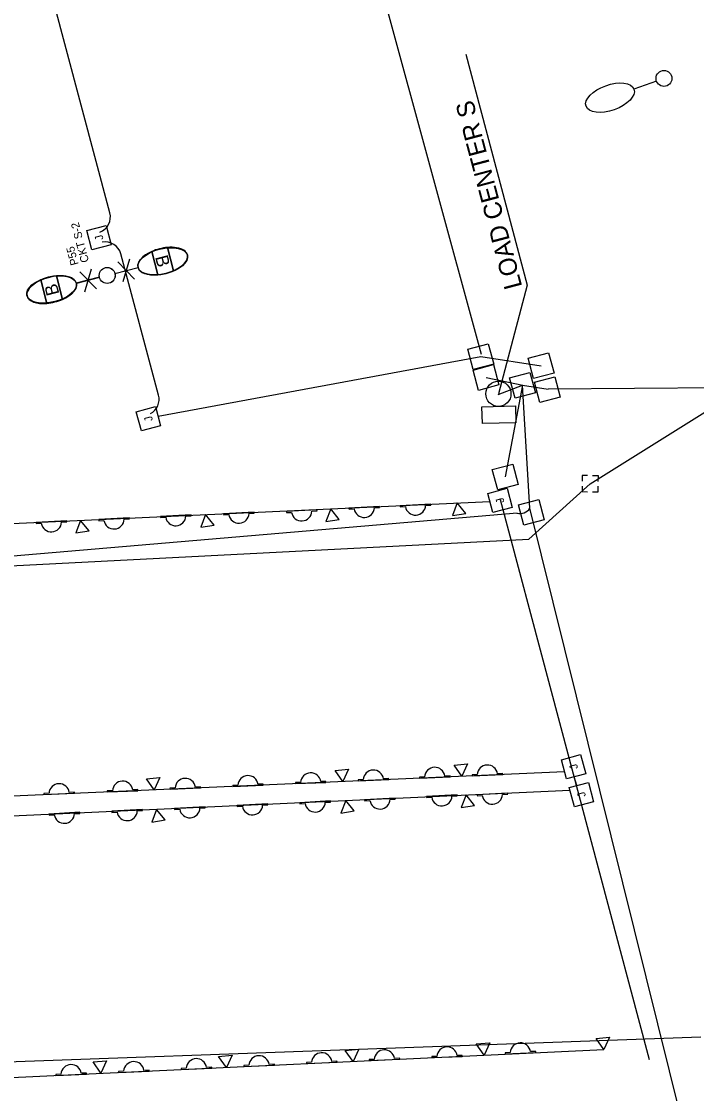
# Model space of a CAD drawing. Extents: x 925407 to 931638, y 609358 to 637063.
# Drawn here: x 930544.2 to 930754.2, y 629284.3 to 629618 of the extents above; entities that cross this region are included whole.
import ezdxf

# ---------------------------------------------------------------- set-up
doc = ezdxf.new("R2010")
doc.units = 0
for name, color, linetype in [('ActivePointCell_dp', 7, 'Continuous'), ('Bridge', 7, 'Continuous'), ('Conduit', 7, 'Continuous'), ('ConduitDB', 7, 'Continuous'), ('ConduitJB', 7, 'Continuous'), ('ConduitOT', 7, 'Continuous'), ('JunctBoxA', 7, 'Continuous'), ('LightingMisc', 7, 'Continuous'), ('LoadCenter', 7, 'Continuous'), ('Miscellaneous2', 7, 'Continuous'), ('PoleLight', 7, 'Continuous'), ('PoleLight_ep', 7, 'Continuous'), ('PullBox', 7, 'Continuous'), ('TextLabel', 7, 'Continuous')]:
    doc.layers.add(name, color=color, linetype=linetype)

msp = doc.modelspace()

# ---------------------------------------------------------------- linework, layer by layer
at = {"layer": 'ActivePointCell_dp'}
msp.add_line((930682.43, 629607.84), (930701.48, 629535.86), dxfattribs=at)
msp.add_lwpolyline([(930701.48, 629535.86), (930692.57, 629502.08)], dxfattribs=at)
at = {"layer": 'Bridge'}
msp.add_line((930739.58, 629294.85), (930693.25, 629469.11), dxfattribs=at)
msp.add_line((930739.58, 629294.85), (930693.25, 629469.11), dxfattribs=at)
msp.add_line((930739.58, 629294.85), (930693.25, 629469.11), dxfattribs=at)
at = {"layer": 'Conduit'}
for p, q in [((930721.08, 629474.1), (930780.76, 629511.4)), ((930702, 629456.89), (930721.08, 629474.1)), ((930495.19, 629446.22), (930702, 629456.89)), ((930519.05, 629293.47), (930755.53, 629302.01))]:
    msp.add_line(p, q, dxfattribs=at)
at = {"layer": 'ConduitDB'}
for p, q in [((930586.7, 629495.1), (930687.09, 629513.65)), ((930784.91, 629504.06), (930708.05, 629503.58)), ((930486.25, 629446.88), (930698.37, 629465.04)), ((930749.58, 629276.27), (930702.37, 629466.49))]:
    msp.add_line(p, q, dxfattribs=at)
msp.add_arc((930699.31, 629468.51), 3.66, 254.0135, 326.5788, dxfattribs=at)
at = {"layer": 'ConduitJB'}
for p, q in [((930490.97, 629459.39), (930689.95, 629468.59)), ((930713.18, 629384.45), (930513.24, 629375.62)), ((930716.95, 629380.16), (930716.18, 629382.87)), ((930514.85, 629369.56), (930714.83, 629378.73)), ((930536.26, 629289.06), (930725.41, 629297.99))]:
    msp.add_line(p, q, dxfattribs=at)
at = {"layer": 'ConduitOT'}
for p, q in [((930630.48, 629722.29), (930687.25, 629514.41)), ((930571.71, 629558.43), (930548.86, 629644.47)), ((930586.85, 629501.67), (930575.11, 629545.66)), ((930687.09, 629513.65), (930705.86, 629510.82)), ((930688.72, 629507.17), (930700.2, 629504.81)), ((930692.54, 629501.84), (930700.07, 629504.76)), ((930700.07, 629504.76), (930694.69, 629476.22)), ((930702.37, 629466.49), (930700.07, 629504.76)), ((930700.07, 629504.76), (930708.05, 629503.58))]:
    msp.add_line(p, q, dxfattribs=at)
for centre, start, end in [((930566.88, 629557.14), 289.9661, 14.8904), ((930570.28, 629544.36), 14.8905, 101.353), ((930582.03, 629500.37), 297.939, 15.0625)]:
    msp.add_arc(centre, 5, start, end, dxfattribs=at)
at = {"layer": 'LightingMisc'}
for p, q in [((930616.6, 629465.24), (930607.09, 629464.71)), ((930615.01, 629464.84), (930616.61, 629464.92)), ((930616.61, 629464.92), (930616.6, 629465.24)), ((930636.14, 629465.96), (930626.63, 629465.43)), ((930626.63, 629465.43), (930626.65, 629465.11)), ((930626.65, 629465.11), (930628.25, 629465.2)), ((930634.56, 629465.55), (930636.16, 629465.64)), ((930636.16, 629465.64), (930636.14, 629465.96)), ((930655.58, 629467.04), (930646.08, 629466.51)), ((930646.08, 629466.51), (930646.1, 629466.2)), ((930646.1, 629466.2), (930647.7, 629466.29)), ((930654, 629466.64), (930655.6, 629466.73)), ((930655.6, 629466.73), (930655.58, 629467.04)), ((930671.52, 629467.78), (930662.02, 629467.25)), ((930662.02, 629467.25), (930662.03, 629466.93)), ((930662.03, 629466.93), (930663.63, 629467.02)), ((930669.94, 629467.37), (930671.54, 629467.46)), ((930671.54, 629467.46), (930671.52, 629467.78)), ((930558.27, 629462.55), (930548.77, 629462.02)), ((930548.77, 629462.02), (930548.78, 629461.7)), ((930548.78, 629461.7), (930550.38, 629461.79)), ((930556.69, 629462.14), (930558.29, 629462.23)), ((930558.29, 629462.23), (930558.27, 629462.55)), ((930577.76, 629463.45), (930568.26, 629462.92)), ((930568.26, 629462.92), (930568.28, 629462.6)), ((930568.28, 629462.6), (930569.88, 629462.69)), ((930576.18, 629463.04), (930577.78, 629463.13)), ((930577.78, 629463.13), (930577.76, 629463.45)), ((930596.95, 629464.46), (930587.45, 629463.93)), ((930587.45, 629463.93), (930587.47, 629463.61)), ((930587.47, 629463.61), (930589.07, 629463.7)), ((930595.37, 629464.05), (930596.97, 629464.14)), ((930596.97, 629464.14), (930596.95, 629464.46)), ((930607.09, 629464.71), (930607.11, 629464.4)), ((930607.11, 629464.4), (930608.71, 629464.49)), ((930638.93, 629381.47), (930637.33, 629381.41)), ((930638.94, 629381.16), (930638.93, 629381.47)), ((930650.52, 629382.01), (930648.92, 629381.94)), ((930648.92, 629381.94), (930648.93, 629381.63)), ((930648.93, 629381.63), (930658.45, 629382.02)), ((930658.43, 629382.33), (930656.83, 629382.27)), ((930658.45, 629382.02), (930658.43, 629382.33)), ((930669.61, 629382.86), (930668.01, 629382.79)), ((930668.01, 629382.79), (930668.02, 629382.47)), ((930668.02, 629382.47), (930677.53, 629382.86)), ((930677.52, 629383.18), (930675.92, 629383.11)), ((930677.53, 629382.86), (930677.52, 629383.18)), ((930685.97, 629383.57), (930684.37, 629383.51)), ((930684.37, 629383.51), (930684.38, 629383.19)), ((930684.38, 629383.19), (930693.9, 629383.58)), ((930693.88, 629383.9), (930692.28, 629383.83)), ((930693.9, 629383.58), (930693.88, 629383.9)), ((930560.69, 629378.08), (930559.09, 629378.01)), ((930560.7, 629377.76), (930560.69, 629378.08)), ((930572.51, 629378.56), (930570.91, 629378.5)), ((930570.91, 629378.5), (930570.92, 629378.18)), ((930570.92, 629378.18), (930580.43, 629378.57)), ((930580.42, 629378.89), (930578.82, 629378.82)), ((930580.43, 629378.57), (930580.42, 629378.89)), ((930592.01, 629379.43), (930590.41, 629379.36)), ((930590.41, 629379.36), (930590.42, 629379.04)), ((930590.42, 629379.04), (930599.93, 629379.43)), ((930599.92, 629379.75), (930598.32, 629379.68)), ((930599.93, 629379.43), (930599.92, 629379.75)), ((930611.51, 629380.29), (930609.91, 629380.22)), ((930609.91, 629380.22), (930609.93, 629379.9)), ((930609.93, 629379.9), (930619.44, 629380.29)), ((930619.43, 629380.61), (930617.82, 629380.55)), ((930619.44, 629380.29), (930619.43, 629380.61)), ((930631.02, 629381.15), (930629.42, 629381.08)), ((930629.42, 629381.08), (930629.43, 629380.77)), ((930629.43, 629380.77), (930638.94, 629381.16)), ((930552.78, 629377.76), (930551.18, 629377.69)), ((930551.18, 629377.69), (930551.19, 629377.37)), ((930551.19, 629377.37), (930560.7, 629377.76)), ((930640.31, 629375.36), (930630.81, 629374.83)), ((930630.81, 629374.83), (930630.82, 629374.52)), ((930638.73, 629374.95), (930640.33, 629375.04)), ((930640.33, 629375.04), (930640.31, 629375.36)), ((930660.47, 629376.28), (930650.96, 629375.76)), ((930650.96, 629375.76), (930650.98, 629375.44)), ((930650.98, 629375.44), (930652.58, 629375.53)), ((930658.89, 629375.88), (930660.49, 629375.97)), ((930660.49, 629375.97), (930660.47, 629376.28)), ((930679.71, 629377.26), (930670.21, 629376.74)), ((930670.21, 629376.74), (930670.22, 629376.42)), ((930670.22, 629376.42), (930671.82, 629376.51)), ((930678.13, 629376.86), (930679.73, 629376.95)), ((930679.73, 629376.95), (930679.71, 629377.26)), ((930695.45, 629377.81), (930685.94, 629377.28)), ((930685.94, 629377.28), (930685.96, 629376.96)), ((930685.96, 629376.96), (930687.56, 629377.05)), ((930693.86, 629377.4), (930695.46, 629377.49)), ((930695.46, 629377.49), (930695.45, 629377.81)), ((930562.32, 629371.84), (930552.81, 629371.31)), ((930560.73, 629371.43), (930562.33, 629371.52)), ((930562.33, 629371.52), (930562.32, 629371.84)), ((930581.83, 629372.68), (930572.32, 629372.15)), ((930572.32, 629372.15), (930572.34, 629371.83)), ((930572.34, 629371.83), (930573.94, 629371.92)), ((930580.24, 629372.27), (930581.84, 629372.36)), ((930581.84, 629372.36), (930581.83, 629372.68)), ((930601.32, 629373.57), (930591.82, 629373.04)), ((930591.82, 629373.04), (930591.83, 629372.73)), ((930591.83, 629372.73), (930593.43, 629372.82)), ((930599.74, 629373.17), (930601.34, 629373.25)), ((930601.34, 629373.25), (930601.32, 629373.57)), ((930620.82, 629374.46), (930611.31, 629373.94)), ((930611.31, 629373.94), (930611.33, 629373.62)), ((930611.33, 629373.62), (930612.93, 629373.71)), ((930619.23, 629374.06), (930620.83, 629374.15)), ((930620.83, 629374.15), (930620.82, 629374.46)), ((930630.82, 629374.52), (930632.42, 629374.6)), ((930552.81, 629371.31), (930552.83, 629371)), ((930552.83, 629371), (930554.43, 629371.08)), ((930653.94, 629294.95), (930652.34, 629294.88)), ((930652.34, 629294.88), (930652.35, 629294.57)), ((930652.35, 629294.57), (930661.86, 629294.96)), ((930661.85, 629295.27), (930660.25, 629295.21)), ((930661.86, 629294.96), (930661.85, 629295.27)), ((930673.43, 629295.87), (930671.83, 629295.8)), ((930671.83, 629295.8), (930671.84, 629295.49)), ((930671.84, 629295.49), (930681.35, 629295.88)), ((930681.34, 629296.19), (930679.74, 629296.13)), ((930681.35, 629295.88), (930681.34, 629296.19)), ((930696.26, 629297.09), (930694.66, 629297.03)), ((930694.66, 629297.03), (930694.67, 629296.71)), ((930694.67, 629296.71), (930704.18, 629297.1)), ((930704.17, 629297.42), (930702.57, 629297.35)), ((930704.18, 629297.1), (930704.17, 629297.42)), ((930575.99, 629291.27), (930574.39, 629291.2)), ((930574.4, 629290.88), (930583.91, 629291.27)), ((930583.9, 629291.59), (930582.3, 629291.53)), ((930583.91, 629291.27), (930583.9, 629291.59)), ((930595.48, 629292.19), (930593.87, 629292.12)), ((930593.87, 629292.12), (930593.89, 629291.81)), ((930593.89, 629291.81), (930603.4, 629292.2)), ((930603.39, 629292.51), (930601.78, 629292.45)), ((930603.4, 629292.2), (930603.39, 629292.51)), ((930614.96, 629293.11), (930613.36, 629293.04)), ((930613.36, 629293.04), (930613.38, 629292.73)), ((930613.38, 629292.73), (930622.89, 629293.12)), ((930622.87, 629293.43), (930621.27, 629293.37)), ((930622.89, 629293.12), (930622.87, 629293.43)), ((930634.45, 629294.03), (930632.85, 629293.96)), ((930632.85, 629293.96), (930632.86, 629293.65)), ((930632.86, 629293.65), (930642.38, 629294.04)), ((930642.36, 629294.35), (930640.76, 629294.29)), ((930642.38, 629294.04), (930642.36, 629294.35)), ((930556.5, 629290.35), (930554.9, 629290.28)), ((930554.9, 629290.28), (930554.91, 629289.96)), ((930554.91, 629289.96), (930564.42, 629290.35)), ((930564.41, 629290.67), (930562.81, 629290.61)), ((930564.42, 629290.35), (930564.41, 629290.67)), ((930574.39, 629291.2), (930574.4, 629290.88))]:
    msp.add_line(p, q, dxfattribs=at)
for points in [[(930678.25, 629464.18), (930682.42, 629464.83), (930679.77, 629468.12)], [(930638.91, 629462.36), (930643.08, 629463.01), (930640.43, 629466.3)], [(930561.1, 629458.77), (930565.27, 629459.42), (930562.62, 629462.7)], [(930599.98, 629460.56), (930604.15, 629461.21), (930601.5, 629464.5)], [(930641.79, 629384.85), (930645.99, 629385.23), (930644.22, 629381.4)], [(930678.78, 629386.51), (930682.98, 629386.89), (930681.21, 629383.06)], [(930583.08, 629382.26), (930587.28, 629382.64), (930585.51, 629378.81)], [(930643.55, 629371.6), (930647.72, 629372.25), (930645.07, 629375.53)], [(930680.99, 629373.31), (930685.15, 629373.96), (930682.51, 629377.25)], [(930584.74, 629368.81), (930588.91, 629369.46), (930586.26, 629372.75)], [(930722.98, 629301.45), (930727.18, 629301.83), (930725.42, 629298)], [(930644.93, 629297.7), (930649.14, 629298.08), (930647.37, 629294.25)], [(930685.67, 629299.75), (930689.87, 629300.13), (930688.1, 629296.3)], [(930605.53, 629295.87), (930609.73, 629296.25), (930607.96, 629292.42)], [(930566.49, 629294.13), (930570.69, 629294.52), (930568.92, 629290.69)]]:
    msp.add_lwpolyline(points, close=True, dxfattribs=at)
for centre, start, end in [((930611.84, 629464.98), 188.912, 357.4336), ((930631.39, 629465.69), 188.912, 357.4336), ((930650.83, 629466.78), 188.912, 357.4336), ((930666.77, 629467.51), 188.912, 357.4336), ((930553.52, 629462.28), 188.912, 357.4336), ((930573.01, 629463.19), 188.912, 357.4336), ((930592.2, 629464.19), 188.912, 357.4336), ((930653.69, 629381.82), 8.0885, 176.6101), ((930672.78, 629382.67), 8.0885, 176.6101), ((930689.14, 629383.39), 8.0885, 176.6101), ((930575.67, 629378.38), 8.0885, 176.6101), ((930595.18, 629379.24), 8.0885, 176.6101), ((930614.68, 629380.1), 8.0885, 176.6101), ((930634.19, 629380.96), 8.0885, 176.6101), ((930555.95, 629377.57), 8.0885, 176.6101), ((930635.56, 629375.1), 188.912, 357.4336), ((930655.72, 629376.02), 188.912, 357.4336), ((930674.96, 629377), 188.912, 357.4336), ((930690.69, 629377.54), 188.912, 357.4336), ((930557.56, 629371.58), 188.912, 357.4336), ((930577.07, 629372.41), 188.912, 357.4336), ((930596.57, 629373.31), 188.912, 357.4336), ((930616.06, 629374.2), 188.912, 357.4336), ((930657.11, 629294.76), 8.0885, 176.6101), ((930676.6, 629295.68), 8.0885, 176.6101), ((930699.43, 629296.91), 8.0885, 176.6101), ((930598.64, 629292), 8.0885, 176.6101), ((930618.13, 629292.92), 8.0885, 176.6101), ((930637.62, 629293.84), 8.0885, 176.6101), ((930559.67, 629290.16), 8.0885, 176.6101), ((930579.16, 629291.08), 8.0885, 176.6101)]:
    msp.add_arc(centre, 3.17, start, end, dxfattribs=at)
at = {"layer": 'LoadCenter'}
for p, q in [((930687.45, 629498.05), (930697.9, 629498.32)), ((930697.9, 629498.32), (930698.04, 629493.09)), ((930687.58, 629492.82), (930687.45, 629498.05)), ((930698.04, 629493.09), (930687.58, 629492.82))]:
    msp.add_line(p, q, dxfattribs=at)
msp.add_circle((930692.57, 629502.1), 3.92, dxfattribs=at)
at = {"layer": 'Miscellaneous2'}
for p, q in [((930584.79, 629546.4), (930584.79, 629546.4)), ((930584.79, 629546.4), (930586.66, 629539.12)), ((930591.5, 629540.36), (930589.63, 629547.64)), ((930589.63, 629547.64), (930589.63, 629547.64)), ((930556.99, 629531.48), (930555.11, 629538.76)), ((930555.11, 629538.76), (930555.11, 629538.76)), ((930550.27, 629537.51), (930550.27, 629537.51)), ((930550.27, 629537.51), (930552.14, 629530.24))]:
    msp.add_line(p, q, dxfattribs=at)
for centre, start_param, end_param in [((930588.15, 629543.38), 1.249648, 1.891946), ((930553.63, 629534.5), 1.249648, 1.891946), ((930588.15, 629543.38), 4.391271, 5.033538), ((930588.15, 629543.38), 4.391241, 4.391271), ((930553.63, 629534.5), 4.391271, 5.033538), ((930553.63, 629534.5), 4.391241, 4.391271)]:
    msp.add_ellipse(centre, major_axis=(7.67, 1.97), ratio=0.5, start_param=start_param, end_param=end_param, dxfattribs=at)
at = {"layer": 'PoleLight'}
for p, q in [((930586.66, 629539.12), (930584.79, 629546.4)), ((930589.63, 629547.64), (930591.5, 629540.36)), ((930555.11, 629538.76), (930556.99, 629531.48)), ((930568.49, 629538.32), (930561.3, 629536.47)), ((930573.28, 629539.56), (930580.47, 629541.41)), ((930552.14, 629530.24), (930550.27, 629537.51))]:
    msp.add_line(p, q, dxfattribs=at)
msp.add_circle((930570.89, 629538.94), 2.48, dxfattribs=at)
msp.add_circle((930570.89, 629538.94), 2.48, dxfattribs=at)
for centre in [(930588.15, 629543.38), (930553.63, 629534.5)]:
    msp.add_ellipse(centre, major_axis=(7.67, 1.97), ratio=0.5, dxfattribs=at)
for centre, start_param, end_param in [((930588.15, 629543.38), 1.891945, 4.391241), ((930588.15, 629543.38), 0.847605, 1.249648), ((930588.15, 629543.38), 5.033538, 6.283185), ((930588.15, 629543.38), 0, 0.847605), ((930553.63, 629534.5), 0.847605, 1.249648), ((930553.63, 629534.5), 0, 0.847605), ((930553.63, 629534.5), 1.891945, 4.391241), ((930553.63, 629534.5), 5.033538, 6.283185)]:
    msp.add_ellipse(centre, major_axis=(7.67, 1.97), ratio=0.5, start_param=start_param, end_param=end_param, dxfattribs=at)
at = {"layer": 'PoleLight_ep'}
for p, q in [((930741.74, 629599.42), (930734.75, 629596.92)), ((930579.37, 629537.8), (930574.21, 629543.14)), ((930577.81, 629544.04), (930575.77, 629536.9)), ((930568.47, 629538.34), (930561.27, 629536.54)), ((930562.37, 629540.08), (930567.53, 629534.75)), ((930563.93, 629533.85), (930565.97, 629540.99)), ((930573.27, 629539.55), (930580.47, 629541.35))]:
    msp.add_line(p, q, dxfattribs=at)
for centre, radius in [((930744.07, 629600.25), 2.47), ((930570.87, 629538.94), 2.48)]:
    msp.add_circle(centre, radius, dxfattribs=at)
for centre, major_axis in [((930727.29, 629594.25), (-7.46, -2.67)), ((930588.16, 629543.28), (7.68, 1.93)), ((930553.59, 629534.61), (-7.68, -1.93))]:
    msp.add_ellipse(centre, major_axis=major_axis, ratio=0.5, dxfattribs=at)
at = {"layer": 'PullBox'}
for p, q in [((930564.55, 629552.88), (930570.54, 629554.47)), ((930566.15, 629546.89), (930564.55, 629552.88)), ((930570.54, 629554.47), (930572.13, 629548.48)), ((930572.13, 629548.48), (930566.15, 629546.89)), ((930683.08, 629515.98), (930689.41, 629517.66)), ((930684.77, 629509.65), (930683.08, 629515.98)), ((930689.41, 629517.66), (930691.1, 629511.33)), ((930701.85, 629513.15), (930708.18, 629514.83)), ((930708.18, 629514.83), (930709.87, 629508.5)), ((930703.54, 629506.82), (930701.85, 629513.15)), ((930684.72, 629509.49), (930691.05, 629511.18)), ((930686.4, 629503.16), (930684.72, 629509.49)), ((930691.1, 629511.33), (930684.77, 629509.65)), ((930691.05, 629511.18), (930692.73, 629504.85)), ((930696.06, 629507.08), (930702.39, 629508.77)), ((930702.39, 629508.77), (930704.07, 629502.44)), ((930709.87, 629508.5), (930703.54, 629506.82)), ((930692.73, 629504.85), (930686.4, 629503.16)), ((930697.74, 629500.75), (930696.06, 629507.08)), ((930703.81, 629505.67), (930710.14, 629507.35)), ((930705.49, 629499.34), (930703.81, 629505.67)), ((930710.14, 629507.35), (930711.82, 629501.02)), ((930704.07, 629502.44), (930697.74, 629500.75)), ((930711.82, 629501.02), (930705.49, 629499.34)), ((930579.92, 629496.5), (930585.9, 629498.09)), ((930581.51, 629490.52), (930579.92, 629496.5)), ((930585.9, 629498.09), (930587.49, 629492.11)), ((930587.49, 629492.11), (930581.51, 629490.52)), ((930690.68, 629478.54), (930697.01, 629480.22)), ((930692.36, 629472.21), (930690.68, 629478.54)), ((930697.01, 629480.22), (930698.69, 629473.9)), ((930689.29, 629471.08), (930695.27, 629472.67)), ((930698.69, 629473.9), (930692.36, 629472.21)), ((930695.27, 629472.67), (930696.86, 629466.69)), ((930690.88, 629465.1), (930689.29, 629471.08)), ((930698.81, 629467.56), (930705.14, 629469.24)), ((930705.14, 629469.24), (930706.83, 629462.91)), ((930696.86, 629466.69), (930690.88, 629465.1)), ((930700.5, 629461.23), (930698.81, 629467.56)), ((930706.83, 629462.91), (930700.5, 629461.23)), ((930712.18, 629388.22), (930718.16, 629389.81)), ((930713.77, 629382.23), (930712.18, 629388.22)), ((930718.16, 629389.81), (930719.75, 629383.83)), ((930719.75, 629383.83), (930713.77, 629382.23)), ((930714.62, 629379.54), (930720.6, 629381.13)), ((930716.21, 629373.55), (930714.62, 629379.54)), ((930720.6, 629381.13), (930722.19, 629375.14)), ((930722.19, 629375.14), (930716.21, 629373.55))]:
    msp.add_line(p, q, dxfattribs=at)
for points in [[(930720.33, 629476.62), (930718.66, 629476.63), (930718.64, 629474.87)], [(930723.64, 629474.82), (930723.66, 629476.59), (930721.89, 629476.6)], [(930718.63, 629473.37), (930718.61, 629471.64), (930720.29, 629471.62)], [(930721.84, 629471.61), (930723.61, 629471.59)], [(930723.61, 629471.59), (930723.63, 629473.32)]]:
    msp.add_lwpolyline(points, dxfattribs=at)

# ---------------------------------------------------------------- texts
at = {"layer": 'ActivePointCell_dp'}
for s, height, rotation, p in [('LOAD CENTER S', 5.6, 104.8256, (930700.03, 629535.48)), ('CKT S-2', 2.5, 104.7826, (930565.24, 629543.29)), ('P55', 2.5, 104.7826, (930562.01, 629542.44))]:
    msp.add_text(s, height=height, rotation=rotation, dxfattribs=at).set_placement(p)
at = {"layer": 'JunctBoxA'}
for p in [(930569.76, 629550.19), (930585.12, 629493.81), (930694.49, 629468.39), (930717.38, 629385.53), (930719.82, 629376.85)]:
    msp.add_text('J', height=2.48, rotation=104.8905, dxfattribs=at).set_placement(p)
at = {"layer": 'TextLabel'}
for rotation, p in [(284.4307, (930585.75, 629544.65)), (104.4307, (930556.02, 629533.23))]:
    msp.add_text('B', height=4, rotation=rotation, dxfattribs=at).set_placement(p)

doc.saveas('drawing.dxf')
